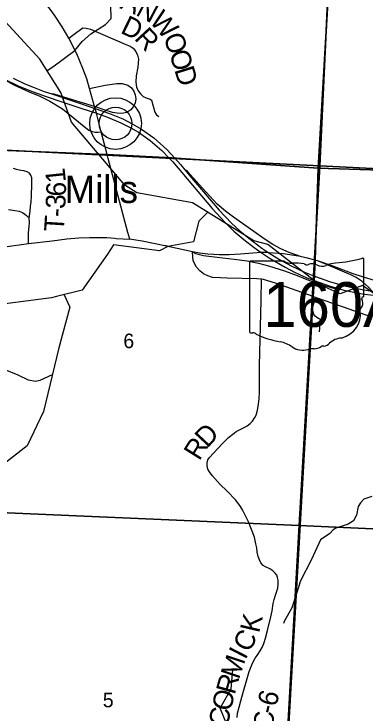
# Model space of a CAD drawing. Extents: x 1878108 to 2183446, y 146837 to 508383.
# Drawn here: x 2042273 to 2047624, y 300413 to 311060 of the extents above; entities that cross this region are included whole.
import ezdxf

# ---------------------------------------------------------------- set-up
doc = ezdxf.new("R2010")
doc.units = 0
for name, color, linetype in [('GM_X_County_Road', 7, 'Continuous'), ('GM_X_County_Road_Text', 7, 'Continuous'), ('GM_X_Interchange_Ramps', 7, 'Continuous'), ('GM_X_Minor_River', 7, 'Continuous'), ('GM_X_Section', 7, 'Continuous'), ('GM_X_Section_Text', 7, 'Continuous'), ('GM_X_State_Location', 7, 'Continuous'), ('GM_X_State_Route', 7, 'Continuous'), ('GM_X_State_Shield', 7, 'Continuous'), ('GM_X_Township', 7, 'Continuous'), ('GM_X_Township_Road', 7, 'Continuous'), ('GM_X_Township_Road_Text', 7, 'Continuous'), ('GM_X_Township_Subdivision', 7, 'Continuous'), ('GM_X_Unincorporated', 7, 'Continuous'), ('GM_X_Unincorporated_Location', 7, 'Continuous'), ('GM_X_Unincorporated_Text', 7, 'Continuous'), ('GM_X_US_Route', 7, 'Continuous')]:
    doc.layers.add(name, color=color, linetype=linetype)

msp = doc.modelspace()

# ---------------------------------------------------------------- linework, layer by layer
at = {"layer": 'GM_X_County_Road'}
for points in [[(2042131, 307519), (2042493, 307567), (2042853, 307612), (2043076, 307640), (2043258, 307654), (2043419, 307660), (2043589, 307661), (2043683, 307658), (2043806, 307648), (2043826, 307647)], [(2043826, 307647), (2044032, 307634)], [(2045668, 300359), (2045673, 300426), (2045694, 300516), (2045723, 300613), (2045760, 300762), (2045805, 300917), (2045849, 301057), (2045889, 301159), (2045914, 301215), (2045937, 301260), (2045968, 301304), (2046016, 301373), (2046049, 301432), (2046070, 301486), (2046098, 301566), (2046128, 301681), (2046179, 301892), (2046197, 301982), (2046212, 302094), (2046227, 302154), (2046255, 302236), (2046282, 302325), (2046291, 302393), (2046288, 302448), (2046281, 302489), (2046268, 302526), (2046243, 302556), (2046206, 302591), (2046160, 302621), (2046096, 302649), (2046061, 302672), (2046027, 302711), (2046005, 302756), (2045986, 302810), (2045971, 302876), (2045963, 302938), (2045951, 303002), (2045928, 303100), (2045885, 303218), (2045836, 303337), (2045789, 303439), (2045745, 303518), (2045717, 303571), (2045647, 303664), (2045508, 303805), (2045409, 303903), (2045286, 304041), (2045246, 304095), (2045222, 304138), (2045209, 304187), (2045207, 304235), (2045220, 304278), (2045242, 304311), (2045377, 304455), (2045439, 304523), (2045536, 304616), (2045601, 304669), (2045652, 304707), (2045721, 304744), (2045773, 304769), (2045819, 304794), (2045861, 304830), (2045900, 304869), (2045936, 304920), (2045953, 304959), (2045971, 305013), (2045982, 305060), (2045991, 305125), (2045998, 305213), (2046003, 305301), (2046003, 305377), (2046003, 305547), (2046003, 305711), (2046030, 306703), (2046038, 307024)]]:
    msp.add_lwpolyline(points, dxfattribs=at)
at = {"layer": 'GM_X_Interchange_Ramps'}
for points in [[(2042104, 310084), (2042135, 310056), (2042269, 309984), (2042505, 309878), (2042666, 309812), (2042817, 309736), (2043008, 309615), (2043195, 309467), (2043341, 309347), (2043410, 309295), (2043462, 309273), (2043509, 309263), (2043549, 309264), (2043597, 309270)], [(2043419, 309929), (2043660, 309975), (2043837, 310002), (2043918, 310002), (2044001, 309977), (2044057, 309935), (2044093, 309887), (2044117, 309829), (2044125, 309767), (2044113, 309703), (2044086, 309648), (2044050, 309604), (2043987, 309562), (2043913, 309546), (2043842, 309550), (2043771, 309564), (2043642, 309603), (2043525, 309643), (2043497, 309651), (2043278, 309721), (2042882, 309842), (2042846, 309844)], [(2046644, 307368), (2046458, 307432), (2046331, 307487), (2046206, 307554), (2046076, 307640), (2045917, 307753), (2045611, 307970), (2045486, 308063), (2045361, 308169), (2045139, 308412), (2044955, 308615), (2044905, 308674), (2044871, 308691)], [(2044988, 307442), (2045033, 307418), (2045155, 307387), (2045361, 307360), (2045620, 307331), (2045816, 307303), (2045989, 307268), (2046144, 307230), (2046384, 307154), (2046577, 307082), (2046726, 307021), (2046837, 306981), (2046902, 306957), (2047007, 306927), (2047082, 306905), (2047167, 306882), (2047220, 306879)], [(2049373, 306892), (2049322, 306900), (2048857, 306867), (2048669, 306869), (2048497, 306875), (2048339, 306891), (2048170, 306915), (2047978, 306949), (2047770, 307000), (2047573, 307062), (2047429, 307110), (2047111, 307231), (2046903, 307301)]]:
    msp.add_lwpolyline(points, dxfattribs=at)
at = {"layer": 'GM_X_Minor_River'}
for points in [[(2042778, 310198), (2042865, 310255), (2043199, 310504), (2043309, 310643), (2043443, 310757), (2043666, 310900), (2043752, 310991), (2043746, 311181), (2043772, 311238), (2043968, 311350), (2044136, 311405), (2044372, 311525), (2044711, 311656), (2044945, 311709), (2045235, 311741), (2045305, 311787), (2045395, 311894), (2045501, 311956), (2045549, 311982), (2045655, 312049), (2045966, 312334), (2046134, 312461)], [(2047830, 306749), (2047573, 306929), (2047230, 306802), (2046911, 306944), (2046132, 307552), (2045920, 307612), (2044985, 308187), (2044141, 308338), (2043959, 308458), (2043145, 309417), (2042986, 309865), (2042667, 310375), (2041957, 311140)], [(2045217, 308044), (2045085, 307911), (2045003, 307594), (2044613, 307522), (2044483, 307455), (2043785, 307547), (2043692, 307406), (2043307, 306857), (2042921, 306762), (2042842, 306743)], [(2042842, 306743), (2042015, 306637), (2041355, 306523), (2041009, 306588), (2040935, 306594), (2039993, 306561), (2038956, 306357), (2038526, 306267), (2037930, 306414), (2036858, 306284), (2036408, 306066), (2035815, 306141), (2035127, 306538), (2034739, 306480), (2034430, 306431), (2034090, 306737), (2033777, 306778), (2032698, 306366), (2031671, 305949), (2031605, 305919), (2030708, 305979)], [(2043035, 306790), (2043122, 306599), (2042955, 305984), (2042721, 305016), (2042472, 304493), (2042005, 304132), (2041620, 303842), (2041254, 303223), (2040760, 302996), (2040232, 302589), (2039625, 302106), (2039319, 302206), (2039043, 301264), (2039099, 300657), (2039283, 300224), (2039278, 300147), (2039450, 299233), (2039238, 298718), (2038749, 298465), (2038551, 298434)], [(2042855, 305571), (2042665, 305486), (2042601, 305472), (2042491, 305490), (2042337, 305564), (2042139, 305648)], [(2047712, 303723), (2047592, 303679), (2047540, 303624), (2047504, 303570), (2047478, 303438), (2047434, 303353), (2047354, 303301), (2047166, 303237), (2047125, 303216), (2047073, 303160), (2046933, 303060), (2046797, 302764), (2046627, 302439), (2046569, 302248), (2046499, 302027), (2046382, 301822), (2046370, 301790)], [(2046179, 296286), (2046081, 297235), (2045750, 297380), (2045524, 297694), (2045519, 298037), (2045608, 298419), (2045567, 299110), (2045562, 300117), (2045409, 300499), (2045575, 300797), (2045599, 301084)]]:
    msp.add_lwpolyline(points, dxfattribs=at)
at = {"layer": 'GM_X_Section'}
for points in [[(2041709, 314236), (2047167, 313959), (2046922, 308751), (2041425, 309022)], [(2047167, 313959), (2052710, 313676), (2052416, 308472), (2046922, 308751)], [(2046922, 308751), (2046609, 303278), (2041118, 303517), (2041425, 309022)], [(2052416, 308472), (2052099, 303033), (2046609, 303278), (2046922, 308751)], [(2046609, 303278), (2046305, 297866), (2040795, 298103), (2041118, 303517)], [(2046609, 303278), (2052099, 303033), (2051726, 297627), (2046305, 297866)]]:
    msp.add_lwpolyline(points, close=True, dxfattribs=at)
at = {"layer": 'GM_X_State_Route'}
for points in [[(2043040, 310804), (2043003, 310866), (2042887, 311040), (2042823, 311133), (2042722, 311261), (2042611, 311396), (2042325, 311732)], [(2043526, 309550), (2043506, 309621), (2043497, 309651), (2043419, 309929), (2043378, 310072), (2043318, 310233), (2043226, 310453), (2043104, 310690), (2043070, 310753), (2043040, 310804)], [(2043703, 308860), (2043687, 308921), (2043597, 309270), (2043526, 309550)], [(2044004, 307736), (2043964, 307886), (2043944, 307962), (2043703, 308860)], [(2044587, 307531), (2044567, 307536), (2044222, 307605), (2044094, 307623), (2044032, 307634), (2044004, 307736)], [(2044988, 307442), (2044639, 307519), (2044587, 307531)], [(2045310, 307400), (2045222, 307406), (2045093, 307422), (2044988, 307442)], [(2047681, 306457), (2047539, 306510), (2047266, 306607), (2046857, 306747), (2046819, 306761), (2046246, 306964), (2046133, 307000), (2046067, 307019), (2046038, 307024), (2046023, 307026), (2045963, 307030), (2045515, 307044), (2045414, 307047), (2045290, 307053), (2045220, 307075), (2045155, 307109), (2045098, 307154), (2045048, 307208), (2045020, 307256), (2044997, 307311), (2044989, 307366), (2044988, 307442)], [(2046030, 307433), (2045715, 307409), (2045543, 307399), (2045393, 307396), (2045310, 307400)], [(2046367, 307412), (2046149, 307429), (2046099, 307433), (2046030, 307433)], [(2046598, 307376), (2046367, 307412)], [(2047775, 306776), (2047743, 306820), (2047719, 306845), (2047663, 306905), (2047619, 306946), (2047564, 306991), (2047476, 307050), (2047392, 307093), (2047263, 307148), (2047085, 307222), (2046903, 307301), (2046851, 307315), (2046713, 307351), (2046644, 307368), (2046598, 307376)]]:
    msp.add_lwpolyline(points, dxfattribs=at)
at = {"layer": 'GM_X_State_Shield'}
for p, q in [((2045853, 307283), (2045853, 306226)), ((2046380, 307301), (2045870, 307301)), ((2047593, 306774), (2047593, 307327)), ((2047593, 306775), (2047593, 306774))]:
    msp.add_line(p, q, dxfattribs=at)
for centre, major_axis, start_param, end_param in [((2045873, 307285), (20.2, 0), 1.712693, 3.28349), ((2046501, 307424), (196, 0), 4.042523, 4.731795), ((2046974, 308742), (1845, 0), 4.814394, 5.042369), ((2047574, 307329), (19.4, 0), 6.141152, 7.989035), ((2046566, 306708), (702, 0), 1.404758, 1.657858), ((2046726, 307291), (56.4, 0), 3.836095, 5.185415), ((2046808, 307168), (117, 0), 0.950623, 2.079405), ((2046960, 307336), (141, 0), 4.081561, 5.145723), ((2047209, 306978), (371, 0), 1.699011, 2.107814), ((2047589, 306734), (30, 0), 1.883978, 3.671073), ((2047573, 306772), (20.7, 0), 5.05454, 6.418171), ((2047398, 306664), (180, 0), 5.934695, 6.695948), ((2047077, 306473), (462, 0), 5.101752, 6.440018), ((2047663, 306543), (131, 0), 2.387724, 3.262537), ((2045873, 306224), (20.3, 0), 3.00124, 4.508301), ((2045876, 306332), (155, 0), 4.665946, 4.897461), ((2045908, 306165), (56, 0), 0.519207, 1.627899), ((2046615, 307115), (1333, 0), 4.195997, 4.488961), ((2047272, 305929), (253, 0), 1.647645, 2.488434), ((2046217, 305751), (417, 0), 0.823519, 1.323587), ((2046841, 306081), (141, 0), 4.691044, 5.507374), ((2046968, 305978), (39.7, 0), 1.147584, 2.315152), ((2046951, 306124), (149, 0), 4.937069, 5.64225), ((2046668, 306160), (265, 0), 4.026481, 4.996735), ((2046821, 305795), (217, 0), 1.495662, 1.94098)]:
    msp.add_ellipse(centre, major_axis=major_axis, ratio=0.8, start_param=start_param, end_param=end_param, dxfattribs=at)
at = {"layer": 'GM_X_Township'}
for points in [[(2047300, 315672), (2046896, 308713), (2044671, 308870), (2043687, 308921), (2041417, 309015), (2041247, 309014), (2037098, 309204), (2031112, 309548), (2029101, 309655), (2027751, 309726), (2027032, 309764), (2024940, 309906), (2023383, 310046), (2023252, 310040), (2022929, 310063), (2022792, 310066), (2015762, 310446), (2014499, 310497), (2014658, 312772)], [(2070739, 311675), (2070548, 310380), (2070071, 307971), (2070016, 307670), (2069797, 307675), (2069609, 307677), (2069237, 307696), (2068944, 307708), (2068514, 307729), (2068064, 307747), (2067786, 307749), (2067054, 307787), (2067016, 307794), (2066035, 307839), (2065952, 307842), (2059932, 308140), (2058453, 308205), (2052396, 308422), (2049919, 308617), (2046896, 308713), (2047300, 315672)], [(2041417, 309015), (2043687, 308921), (2044671, 308870), (2046896, 308713), (2046851, 307316), (2046838, 306991), (2046819, 306761), (2046274, 297148), (2046004, 292592), (2045985, 292287), (2045910, 291035), (2045645, 286986), (2045292, 281209), (2045232, 280222), (2044993, 276329), (2043134, 276418), (2042678, 276439), (2039444, 276594)], [(2045292, 281209), (2045645, 286986), (2045910, 291035), (2045985, 292287), (2046004, 292592), (2046274, 297148), (2046819, 306761), (2046838, 306991), (2046851, 307316), (2046896, 308713), (2049919, 308617), (2052396, 308422), (2058453, 308205)]]:
    msp.add_lwpolyline(points, dxfattribs=at)
at = {"layer": 'GM_X_Township_Road'}
for points in [[(2043104, 310690), (2043229, 310781), (2043317, 310847)], [(2043317, 310847), (2043368, 310846), (2043435, 310827), (2043965, 310603), (2044037, 310571), (2044083, 310538), (2044125, 310487), (2044152, 310432), (2044163, 310371), (2044153, 310250), (2044132, 310117), (2044125, 310021), (2044136, 309947), (2044158, 309892), (2044195, 309845), (2044238, 309807), (2044281, 309786), (2044342, 309763), (2044363, 309747), (2044413, 309565), (2044439, 309528), (2044475, 309499)], [(2042493, 307567), (2042491, 307615), (2042492, 307731), (2042505, 307827), (2042507, 307888), (2042502, 307952), (2042516, 308062), (2042525, 308137), (2042533, 308196), (2042537, 308291), (2042544, 308476), (2042543, 308567), (2042530, 308609), (2042507, 308638), (2042471, 308660), (2042423, 308672), (2042376, 308680), (2042308, 308695), (2042264, 308710)], [(2042187, 308084), (2042287, 308069), (2042350, 308059), (2042402, 308042), (2042439, 308017), (2042465, 307997), (2042502, 307952)]]:
    msp.add_lwpolyline(points, dxfattribs=at)
at = {"layer": 'GM_X_Township_Subdivision'}
msp.add_lwpolyline([(2046916, 306226), (2046922, 306283), (2046928, 306345), (2046933, 306392), (2046930, 306415), (2046904, 306428), (2046876, 306444), (2046850, 306465), (2046832, 306489), (2046819, 306525), (2046815, 306560), (2046814, 306596), (2046824, 306642), (2046850, 306720), (2046857, 306747)], dxfattribs=at)
at = {"layer": 'GM_X_Unincorporated'}
for radius in [393, 249]:
    msp.add_circle((2043816, 309394), radius, dxfattribs=at)
at = {"layer": 'GM_X_Unincorporated_Location'}
msp.add_line((2043816, 309394), (2043816, 309394), dxfattribs=at)
at = {"layer": 'GM_X_US_Route'}
for points in [[(2040274, 311669), (2041047, 310902), (2041211, 310741), (2041366, 310595), (2041566, 310430), (2041743, 310304), (2041938, 310180), (2042104, 310084), (2042139, 310064), (2042334, 309969), (2042562, 309876), (2042761, 309805), (2042987, 309729)], [(2042258, 310084), (2042438, 309997), (2042577, 309943), (2042730, 309883), (2042846, 309844), (2043506, 309621), (2043725, 309547), (2043927, 309463), (2044071, 309391), (2044212, 309306), (2044396, 309176), (2044594, 308998), (2044716, 308867), (2044804, 308772), (2044871, 308691), (2044972, 308569), (2045394, 308074), (2045581, 307880), (2045705, 307764), (2045842, 307649), (2046039, 307500), (2046149, 307429), (2046189, 307403), (2046310, 307327), (2046489, 307227), (2046687, 307134), (2046841, 307072), (2046856, 307066), (2047067, 306989), (2047296, 306924), (2047568, 306867), (2047719, 306845)], [(2042987, 309729), (2043291, 309629), (2043526, 309550), (2043696, 309489), (2043896, 309406), (2044051, 309328), (2044164, 309262), (2044344, 309137), (2044520, 308984), (2044627, 308872), (2044662, 308836)], [(2044662, 308836), (2044685, 308812), (2044907, 308552), (2045286, 308102), (2045476, 307894), (2045617, 307755), (2045767, 307628), (2045922, 307506), (2046030, 307433), (2046169, 307339), (2046396, 307207), (2046536, 307135), (2046669, 307072), (2046750, 307039)], [(2046750, 307039), (2046810, 307014), (2046838, 307004), (2046995, 306948), (2047094, 306915), (2047220, 306879), (2047288, 306860), (2047564, 306804), (2047775, 306776), (2047926, 306758), (2048106, 306750), (2048246, 306750), (2048334, 306752), (2048535, 306761), (2048672, 306772)]]:
    msp.add_lwpolyline(points, dxfattribs=at)

# ---------------------------------------------------------------- texts
at = {"layer": 'GM_X_County_Road_Text'}
for s, rotation, p in [('D', 46.7493, (2045211, 304449)), ('R', 57.9371, (2045089, 304253)), ('K', 76.9123, (2045997, 301634)), ('C', 61.2195, (2045846, 301335)), ('I', 62.8345, (2045791, 301227)), ('M', 71.3577, (2045691, 300929)), ('R', 74.4803, (2045627, 300696)), ('O', 76.2067, (2045564, 300442)), ('6', 75.1444, (2046257, 300511)), ('C', 80.5511, (2045525, 300205)), ('-', 75.8093, (2046227, 300393)), ('C', 86.4285, (2046214, 300163))]:
    msp.add_text(s, height=300, rotation=rotation, dxfattribs=at).set_placement(p)
at = {"layer": 'GM_X_Section_Text'}
for s, p in [('6', (2043935, 305977)), ('5', (2043623, 300515))]:
    msp.add_text(s, height=221, rotation=0, dxfattribs=at).set_placement(p)
at = {"layer": 'GM_X_State_Location'}
msp.add_text('160A', height=1, rotation=0, dxfattribs=at).set_placement((2046280, 306640))
for s in ['s', 'r']:
    msp.add_text(s, height=1, dxfattribs=at).set_placement((2046704, 306684))
at = {"layer": 'GM_X_State_Shield'}
msp.add_text('160A', height=680, dxfattribs=at).set_placement((2046064, 306301))
at = {"layer": 'GM_X_Township_Road_Text'}
for s, rotation, p in [('A', 337.0736, (2043872, 311150)), ('N', 332.0452, (2044109, 311050)), ('W', 311.5274, (2044320, 310944)), ('D', 334.2153, (2043877, 310779)), ('R', 313.0595, (2044091, 310681)), ('O', 291.1466, (2044536, 310708)), ('O', 286.9787, (2044629, 310467)), ('D', 287.1462, (2044707, 310213)), ('1', 95.886, (2043063, 308507)), ('6', 88.4626, (2043060, 308281)), ('3', 87.0657, (2043050, 308090)), ('-', 86.4472, (2043042, 307965)), ('T', 86.3922, (2043028, 307741))]:
    msp.add_text(s, height=300, rotation=rotation, dxfattribs=at).set_placement(p)
at = {"layer": 'GM_X_Unincorporated_Text'}
msp.add_text('Mills', height=417, rotation=0, dxfattribs=at).set_placement((2043042, 308185))

doc.saveas('drawing.dxf')
